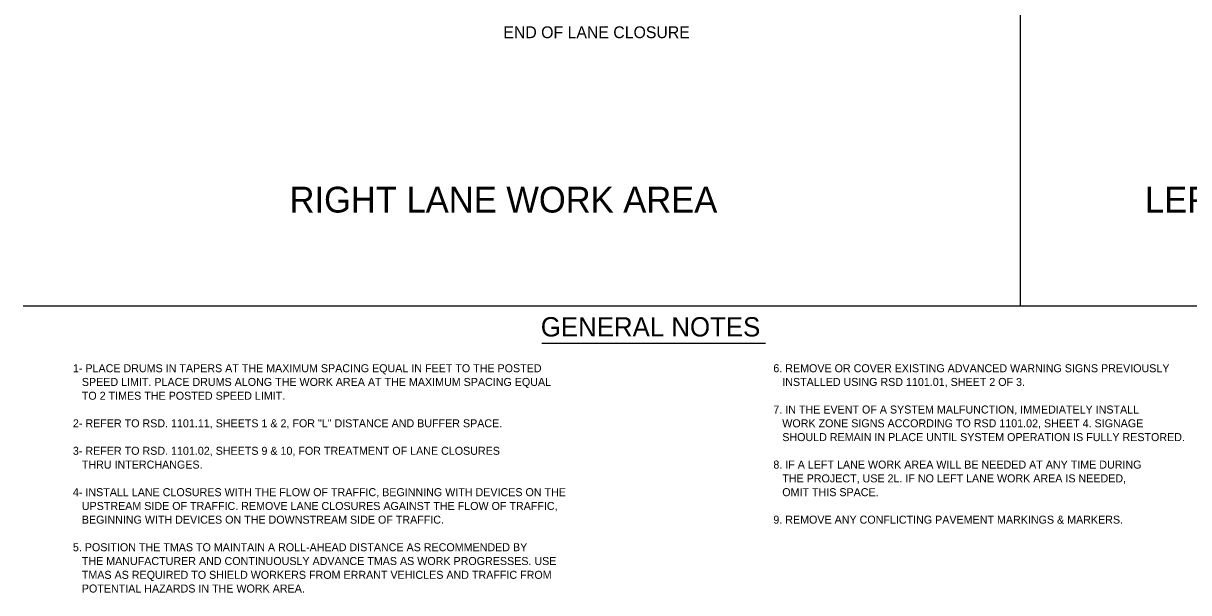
# Model space of a CAD drawing. Extents: x 1379436 to 1387057, y 792703 to 795604.
# Drawn here: x 1384811 to 1386121, y 794201 to 794841 of the extents above; entities that cross this region are included whole.
import ezdxf

# ---------------------------------------------------------------- set-up
doc = ezdxf.new("R2010")
doc.units = 0
for name, color, linetype in [('Default', 7, 'Continuous'), ('Prop Mkg Solid White Lane Line', 7, 'Continuous'), ('Text', 7, 'Continuous')]:
    doc.layers.add(name, color=color, linetype=linetype)

msp = doc.modelspace()

# ---------------------------------------------------------------- linework, layer by layer
at = {"layer": 'Default'}
for p, q in [((1385931.8, 794523.6), (1385931.8, 795173.4)), ((1384810.5, 794523.6), (1386228.1, 794523.6))]:
    msp.add_line(p, q, dxfattribs=at)
at = {"layer": 'Prop Mkg Solid White Lane Line'}
msp.add_line((1385393.5, 794481.4), (1385645.2, 794481.4), dxfattribs=at)

# ---------------------------------------------------------------- texts
at = {"layer": 'Default'}
for s, p in [('RIGHT LANE WORK AREA', (1385109.9, 794628.4)), ('LEFT LANE WORK AREA', (1386071.7, 794628.4))]:
    msp.add_text(s, height=29.027, dxfattribs=at).set_placement(p)
at = {"layer": 'Prop Mkg Solid White Lane Line'}
msp.add_text('GENERAL NOTES', height=21.707, dxfattribs=at).set_placement((1385392.4, 794489.1))
at = {"layer": 'Text'}
for s, height, p in [('END OF LANE CLOSURE', 13.31, (1385350.3, 794824.4)), ('1- PLACE DRUMS IN TAPERS AT THE MAXIMUM SPACING EQUAL IN FEET TO THE POSTED', 9, (1384866.3, 794448.9)), ('6. REMOVE OR COVER EXISTING ADVANCED WARNING SIGNS PREVIOUSLY', 9, (1385653.9, 794448.9)), ('   SPEED LIMIT. PLACE DRUMS ALONG THE WORK AREA AT THE MAXIMUM SPACING EQUAL', 9, (1384866.3, 794433.5)), ('   INSTALLED USING RSD 1101.01, SHEET 2 OF 3.', 9, (1385653.9, 794433.5)), ('   TO 2 TIMES THE POSTED SPEED LIMIT.', 9, (1384866.3, 794418)), ('7. IN THE EVENT OF A SYSTEM MALFUNCTION, IMMEDIATELY INSTALL', 9, (1385653.9, 794402.5)), ('2- REFER TO RSD. 1101.11, SHEETS 1 & 2, FOR "L" DISTANCE AND BUFFER SPACE.', 9, (1384866.3, 794387)), ('   WORK ZONE SIGNS ACCORDING TO RSD 1101.02, SHEET 4. SIGNAGE', 9, (1385653.9, 794387)), ('   SHOULD REMAIN IN PLACE UNTIL SYSTEM OPERATION IS FULLY RESTORED.', 9, (1385653.9, 794371.5)), ('3- REFER TO RSD. 1101.02, SHEETS 9 & 10, FOR TREATMENT OF LANE CLOSURES', 9, (1384866.3, 794356.1)), ('   THRU INTERCHANGES.', 9, (1384866.3, 794340.6)), ('8. IF A LEFT LANE WORK AREA WILL BE NEEDED AT ANY TIME DURING', 9, (1385653.9, 794340.6)), ('   THE PROJECT, USE 2L. IF NO LEFT LANE WORK AREA IS NEEDED,', 9, (1385653.9, 794325.1)), ('4- INSTALL LANE CLOSURES WITH THE FLOW OF TRAFFIC, BEGINNING WITH DEVICES ON THE ', 9, (1384866.3, 794309.6)), ('   OMIT THIS SPACE.', 9, (1385653.9, 794309.6)), ('   UPSTREAM SIDE OF TRAFFIC. REMOVE LANE CLOSURES AGAINST THE FLOW OF TRAFFIC, ', 9, (1384866.3, 794294.1)), ('   BEGINNING WITH DEVICES ON THE DOWNSTREAM SIDE OF TRAFFIC.', 9, (1384866.3, 794278.7)), ('9. REMOVE ANY CONFLICTING PAVEMENT MARKINGS & MARKERS.', 9, (1385653.9, 794278.7)), ('5. POSITION THE TMAS TO MAINTAIN A ROLL-AHEAD DISTANCE AS RECOMMENDED BY', 9, (1384866.3, 794247.7)), ('   THE MANUFACTURER AND CONTINUOUSLY ADVANCE TMAS AS WORK PROGRESSES. USE', 9, (1384866.3, 794232.2)), ('   TMAS AS REQUIRED TO SHIELD WORKERS FROM ERRANT VEHICLES AND TRAFFIC FROM', 9, (1384866.3, 794216.7)), ('   POTENTIAL HAZARDS IN THE WORK AREA.', 9, (1384866.3, 794201.3))]:
    msp.add_text(s, height=height, dxfattribs=at).set_placement(p)

doc.saveas('drawing.dxf')
